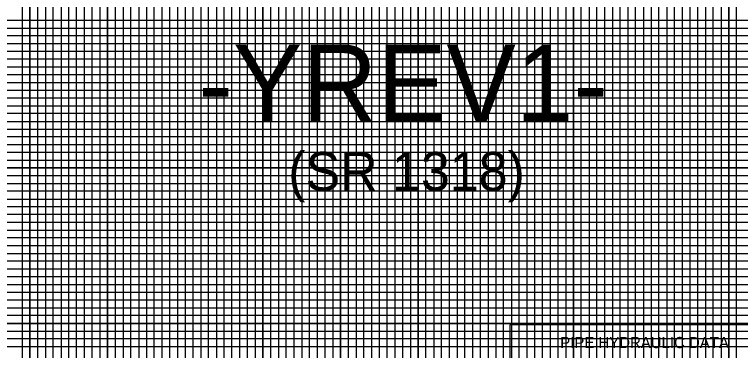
# Model space of a CAD drawing. Extents: x 572269 to 579912, y -56875 to -49627.
# Drawn here: x 574574.7 to 575042.2, y -53065.2 to -52849 of the extents above; entities that cross this region are included whole.
import ezdxf

# ---------------------------------------------------------------- set-up
doc = ezdxf.new("R2010")
doc.units = 0
for name, color, linetype in [('Prop Grid Mask', 7, 'Continuous'), ('Prop PFL Structure Hydraulic Data Label CELL', 7, 'Continuous'), ('Prop PFL Text', 7, 'Continuous'), ('Scratch_Level_3', 7, 'Continuous'), ('Scratch_Level_5', 7, 'Continuous'), ('Scratch_Level_6', 7, 'Continuous'), ('Sheet Cutting Line CELL', 7, 'Continuous'), ('Sheet DOT Grid CELL', 7, 'Continuous'), ('Sheet Profile Grid Major CELL', 7, 'Continuous'), ('Sheet Profile Grid Middle CELL', 7, 'Continuous'), ('Sheet Profile Grid Minor CELL', 7, 'Continuous')]:
    doc.layers.add(name, color=color, linetype=linetype)

# ---------------------------------------------------------------- blocks, each defined once
blk = doc.blocks.new('PROFILE SHEET SINGLE')
at = {"layer": 'Sheet DOT Grid CELL'}
for p, q in [((15, 21), (15, 0.5)), ((16, 21), (16, 0.5)), ((17, 21), (17, 0.5)), ((18, 21), (18, 0.5)), ((19, 21), (19, 0.5)), ((20, 21), (20, 0.5)), ((21, 21), (21, 0.5)), ((22, 21), (22, 0.5)), ((23, 21), (23, 0.5)), ((24, 21), (24, 0.5)), ((0, 18.5), (25.999, 18.5)), ((0, 17.5), (30, 17.5)), ((0, 16.5), (30, 16.5)), ((0, 15.5), (30, 15.5))]:
    blk.add_line(p, q, dxfattribs=at)
at = {"layer": 'Sheet Profile Grid Major CELL'}
for points in [[(15, 21), (15, 0.5), (16, 0.5), (16, 21)], [(17, 21), (17, 0.5), (18, 0.5), (18, 21)], [(19, 21), (19, 0.5), (20, 0.5), (20, 21)], [(21, 21), (21, 0.5), (22, 0.5), (22, 21)], [(23, 21), (23, 0.5), (24, 0.5), (24, 21)], [(30, 17.5), (0, 17.5), (0, 18.5), (25.999, 18.5)], [(30, 15.5), (0, 15.5), (0, 16.5), (30, 16.5)]]:
    blk.add_lwpolyline(points, dxfattribs=at)
at = {"layer": 'Sheet Profile Grid Middle CELL'}
for points in [[(14.5, 21), (14.5, 0.5), (15.5, 0.5), (15.5, 21)], [(16.5, 21), (16.5, 0.5), (17.5, 0.5), (17.5, 21)], [(18.5, 21), (18.5, 0.5), (19.5, 0.5), (19.5, 21)], [(20.5, 21), (20.5, 0.5), (21.5, 0.5), (21.5, 21)], [(22.5, 21), (22.5, 0.5), (23.5, 0.5), (23.5, 21)], [(25.999, 19), (0, 19), (0, 17.999), (30, 17.999)], [(30, 17), (0, 17), (0, 16), (30, 16)]]:
    blk.add_lwpolyline(points, dxfattribs=at)
at = {"layer": 'Sheet Profile Grid Minor CELL'}
for p, q in [((29, 17.4), (1, 17.4)), ((1, 17.3), (29, 17.3)), ((29, 16.9), (1, 16.9))]:
    blk.add_line(p, q, dxfattribs=at)
for points in [[(14.9, 21), (14.9, 0.5), (15.1, 0.5), (15.1, 21)], [(15.2, 21), (15.2, 0.5)], [(15.2, 0.5), (15.3, 0.5), (15.3, 20.988)], [(15.4, 20.988), (15.4, 0.5), (15.6, 0.5), (15.6, 21)], [(15.7, 21), (15.7, 0.5), (15.8, 0.5), (15.8, 21)], [(15.9, 21), (15.9, 0.5), (16.1, 0.5), (16.1, 21)], [(16.2, 21), (16.2, 0.5), (16.3, 0.5), (16.3, 21)], [(16.4, 21), (16.4, 0.5), (16.6, 0.5), (16.6, 21)], [(16.7, 21), (16.7, 0.5), (16.8, 0.5), (16.8, 21)], [(16.9, 21), (16.9, 0.5), (17.1, 0.5), (17.1, 21)], [(17.2, 21), (17.2, 0.5), (17.3, 0.5), (17.3, 21)], [(17.4, 21), (17.4, 0.5), (17.6, 0.5), (17.6, 21)], [(17.7, 21), (17.7, 0.5), (17.8, 0.5), (17.8, 21)], [(17.9, 21), (17.9, 0.5), (18.1, 0.5), (18.1, 21)], [(18.2, 21), (18.2, 0.5), (18.3, 0.5), (18.3, 21)], [(18.4, 21), (18.4, 0.5), (18.6, 0.5), (18.6, 21)], [(18.7, 21), (18.7, 0.5), (18.8, 0.5), (18.8, 21)], [(18.9, 21), (18.9, 0.5), (19.1, 0.5), (19.1, 21)], [(19.2, 21), (19.2, 0.5), (19.3, 0.5), (19.3, 21)], [(19.4, 21), (19.4, 0.5), (19.6, 0.5), (19.6, 21)], [(19.7, 21), (19.7, 0.5), (19.8, 0.5), (19.8, 21)], [(19.9, 21), (19.9, 0.5), (20.1, 0.5), (20.1, 21)], [(20.2, 21), (20.2, 0.5), (20.3, 0.5), (20.3, 21)], [(20.4, 21), (20.4, 0.5), (20.6, 0.5), (20.6, 21)], [(20.7, 21), (20.7, 0.5), (20.8, 0.5), (20.8, 21)], [(20.9, 21), (20.9, 0.5), (21.1, 0.5), (21.1, 21)], [(21.2, 21), (21.2, 0.5), (21.3, 0.5), (21.3, 21)], [(21.4, 21), (21.4, 0.5)], [(21.4, 0.5), (21.6, 0.5), (21.6, 21)], [(21.7, 21), (21.7, 0.5), (21.8, 0.5), (21.8, 21)], [(21.9, 21), (21.9, 0.5), (22.1, 0.5), (22.1, 21)], [(22.2, 21), (22.2, 0.5), (22.3, 0.5), (22.3, 21)], [(22.4, 21), (22.4, 0.5), (22.6, 0.5), (22.6, 21)], [(22.7, 21), (22.7, 0.5), (22.8, 0.5), (22.8, 21)], [(22.9, 21), (22.9, 0.5), (23.1, 0.5), (23.1, 21)], [(23.2, 21), (23.2, 0.5), (23.3, 0.5), (23.3, 21)], [(23.4, 21), (23.4, 0.5), (23.6, 0.5), (23.6, 21)], [(23.7, 21), (23.7, 0.5), (23.8, 0.5), (23.8, 21)], [(23.9, 21), (23.9, 0.5), (24.1, 0.5), (24.1, 21)], [(25.999, 19.4), (1, 19.4), (1, 19.3), (25.999, 19.3)], [(25.999, 19.2), (1, 19.2), (1, 19.1), (25.999, 19.1)], [(25.999, 18.9), (1, 18.9), (1, 18.8), (25.999, 18.8)], [(25.999, 18.7), (1, 18.7), (1, 18.6), (25.999, 18.6)], [(25.999, 18.4), (1, 18.4), (1, 18.3), (25.999, 18.3)], [(29, 18.2), (1, 18.2), (1, 18.2), (1, 17.8), (29, 17.8)], [(1, 18.1), (29, 18.1)], [(29, 17.9), (1, 17.9)], [(29, 17.7), (1, 17.7), (1, 17.6), (29, 17.6)], [(29, 17.2), (1, 17.2), (1, 17.1), (29, 17.1)], [(29, 16.8), (1, 16.8), (1, 16.7), (29, 16.7)], [(29, 16.6), (1, 16.6)], [(1, 16.4), (29, 16.4)], [(29, 16.3), (1, 16.3), (1, 16.2), (29, 16.2)], [(29, 16.1), (1, 16.1), (1, 15.9), (29, 15.9)], [(29, 15.8), (1, 15.8), (1, 15.7), (29, 15.7)], [(29, 15.6), (1, 15.6), (1, 15.4), (29, 15.4)], [(29, 15.3), (1, 15.3), (1, 15.2), (29, 15.2)]]:
    blk.add_lwpolyline(points, dxfattribs=at)

msp = doc.modelspace()

# ---------------------------------------------------------------- linework, layer by layer
at = {"layer": 'Prop Grid Mask'}
msp.add_lwpolyline([(574893.73, -53170.98), (575080.54, -53170.98), (575080.54, -53048.62), (574893.73, -53048.62)], close=True, dxfattribs=at)
at = {"layer": 'Scratch_Level_3'}
msp.add_line((574584.69, -56875.35), (574584.69, -49627.25), dxfattribs=at)
at = {"layer": 'Scratch_Level_5'}
msp.add_line((574784.69, -53797.71), (574784.69, -52363.21), dxfattribs=at)
at = {"layer": 'Scratch_Level_6'}
msp.add_line((574584.69, -54007.71), (574584.69, -52269.82), dxfattribs=at)

# ---------------------------------------------------------------- block references
at = {"layer": 'Sheet Cutting Line CELL', "xscale": 50, "yscale": 50}
msp.add_blockref('PROFILE SHEET SINGLE', (573834.69, -53822.71), dxfattribs=at)

# ---------------------------------------------------------------- texts
at = {"layer": 'Prop PFL Structure Hydraulic Data Label CELL'}
msp.add_text('PIPE HYDRAULIC DATA', height=7.2, rotation=360, dxfattribs=at).set_placement((574926.12, -53063.66))
at = {"layer": 'Prop PFL Text'}
for s, height, p in [('-YREV1- ', 50, (574693.16, -52918.39)), ('(SR 1318)', 25, (574750.99, -52962.38))]:
    msp.add_text(s, height=height, dxfattribs=at).set_placement(p)

doc.saveas('drawing.dxf')
